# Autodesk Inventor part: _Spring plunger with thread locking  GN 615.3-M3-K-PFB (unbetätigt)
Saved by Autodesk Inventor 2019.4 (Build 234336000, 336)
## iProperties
Created: 2021-06
Part Number: _Spring plunger with thread locking  GN 615.3-M3-K-PFB (unbetätigt)
Material: Generic
Document SubType Name: Modeling
Designer: Administrator
Density: 1 g/cm^3
Appearance: Default
Title: _Spring plunger with thread locking  GN 615.3-M3-K-PFB (unbetätigt)
Author: Administrator
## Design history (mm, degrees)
feature "Body1"
body "Solid1"
